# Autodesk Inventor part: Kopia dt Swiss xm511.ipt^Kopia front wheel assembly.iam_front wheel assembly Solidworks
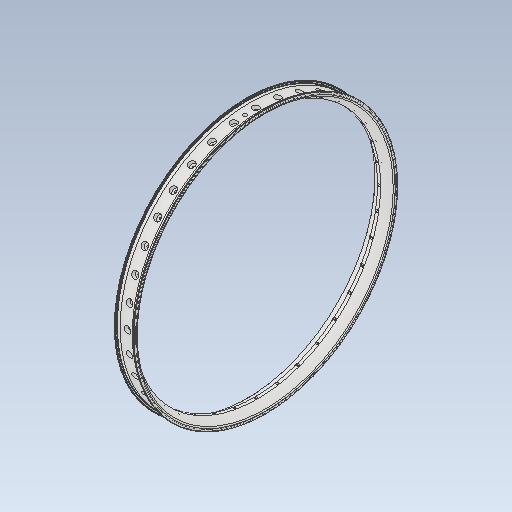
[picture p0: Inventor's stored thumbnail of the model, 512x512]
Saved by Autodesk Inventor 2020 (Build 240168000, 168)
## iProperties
Created: 2017-09
Part Number: Kopia dt Swiss xm511.ipt^Kopia front wheel assembly.iam_front wheel assembly Solidworks
Material: Ogólny
Document SubType Name: Modeling
Designer: Tomasz
Density: 1 g/cm^3
Appearance: Domyślna
Sending System: SolidWorks 2017
Last Author: Tomasz
Last Saved: 2017-09-11
Author: Tomasz
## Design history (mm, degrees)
feature "dt Swiss xm511.ipt"
node "Bryła1"
